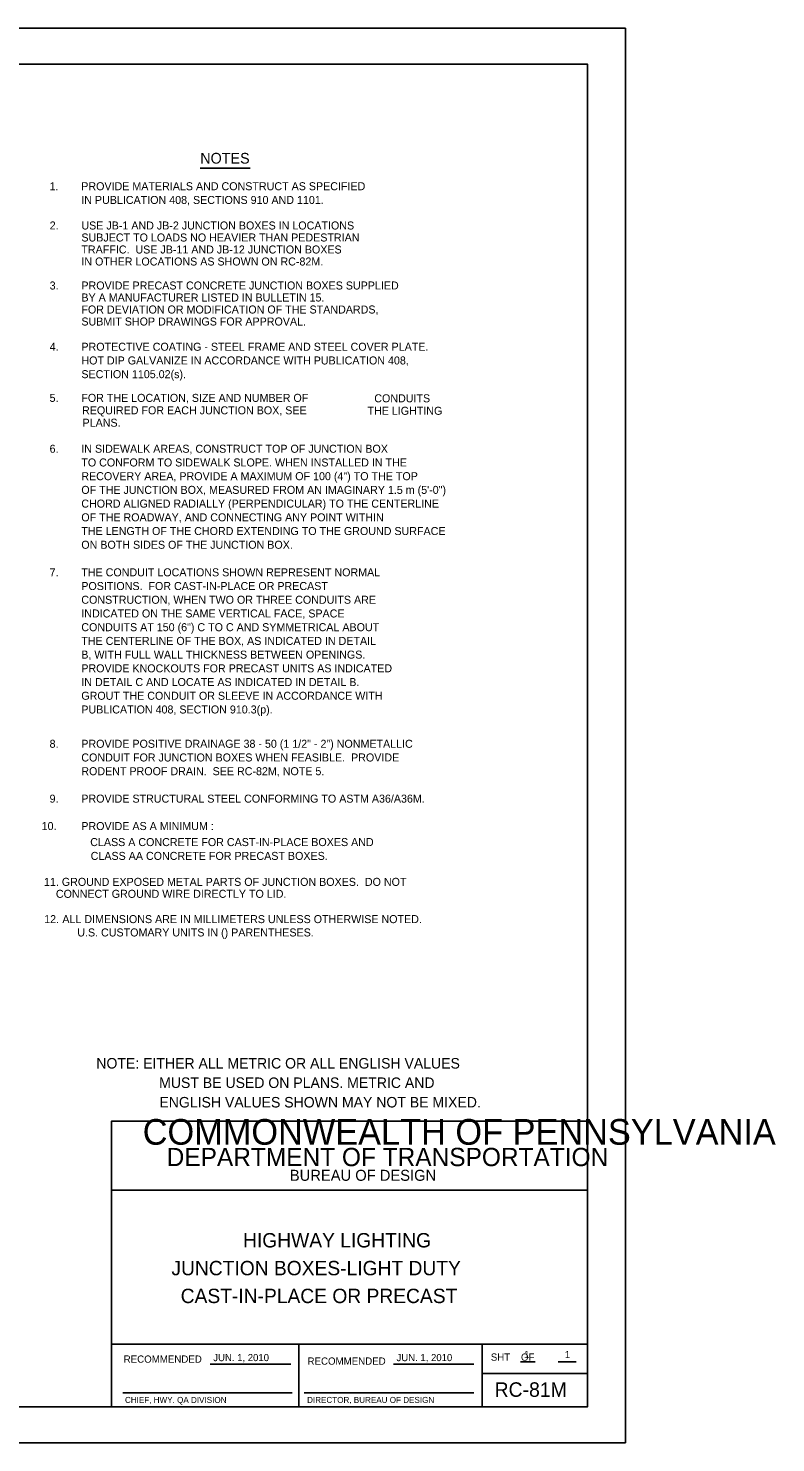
# Model space of a CAD drawing. Extents: x 638447 to 639352, y 298406 to 299000.
# Drawn here: x 639037 to 639352, y 298406 to 299000 of the extents above; entities that cross this region are included whole.
import ezdxf

# ---------------------------------------------------------------- set-up
doc = ezdxf.new("R2010")
doc.units = 0
for name, color, linetype in [('1', 7, 'Continuous'), ('2', 7, 'Continuous'), ('3', 7, 'Continuous'), ('40', 7, 'Continuous'), ('PLT-BNDY', 7, 'Continuous')]:
    doc.layers.add(name, color=color, linetype=linetype)

msp = doc.modelspace()

# ---------------------------------------------------------------- linework, layer by layer
at = {"layer": '1'}
for p, q in [((639113.859625, 298439.4615), (639147.746125, 298439.4615)), ((639190.857625, 298439.4615), (639224.727625, 298439.4615)), ((639244.260125, 298440.4455), (639250.402125, 298440.4455)), ((639260.069625, 298440.4455), (639267.716125, 298440.4455)), ((639077.156625, 298427.428146), (639148.406125, 298427.428146)), ((639153.326125, 298427.428146), (639224.666125, 298427.428146))]:
    msp.add_line(p, q, dxfattribs=at)
msp.add_lwpolyline([(639272.394625, 298421.4725), (639272.394625, 298985.4725), (638486.394625, 298985.4725), (638486.394625, 298421.4725), (639272.394625, 298421.4725), (639272.394625, 298447.8315), (639072.394625, 298447.8315), (639072.394625, 298512.509), (639272.394625, 298512.509), (639272.394625, 298541.4725), (639072.394625, 298541.4725), (639072.394625, 298421.4725), (639151.196125, 298421.4725), (639151.196125, 298447.8315), (639151.196125, 298421.4725), (639228.196125, 298421.4725), (639228.196125, 298447.8315), (639228.196125, 298435.515), (639272.394625, 298435.515)], dxfattribs=at)
at = {"layer": '3'}
msp.add_line((639109.689875, 298941.762), (639130.687875, 298941.762), dxfattribs=at)
at = {"layer": 'PLT-BNDY'}
msp.add_lwpolyline([(638447.394625, 299000.4725), (639288.394625, 299000.4725), (639288.394625, 298406.4725), (638447.394625, 298406.4725)], close=True, dxfattribs=at)

# ---------------------------------------------------------------- texts
at = {"layer": '1'}
for s, height, p in [('12.', 3.36, (639044.140875, 298624.67125)), ('COMMONWEALTH OF PENNSYLVANIA', 10.7833725, (639085.545625, 298531.616)), ('DEPARTMENT OF TRANSPORTATION', 7.6842885, (639095.606625, 298522.62175)), ('BUREAU OF DESIGN', 4.6220925, (639147.381125, 298516.4595)), ('HIGHWAY LIGHTING', 6.0400005, (639127.717125, 298488.4795)), ('JUNCTION BOXES-LIGHT DUTY', 6.0400005, (639097.614375, 298476.7915)), ('CAST-IN-PLACE OR PRECAST', 6.0400005, (639101.507125, 298465.10325)), ('JUN. 1, 2010', 3, (639115.198151, 298440.719402)), ('JUN. 1, 2010', 3, (639192.196151, 298440.719402)), ('SHT    OF', 3.048, (639231.800125, 298440.9025)), ('1', 3.048, (639245.792125, 298441.98675)), ('1', 3.048, (639262.919625, 298441.98675)), ('RECOMMENDED', 3.048, (639077.558125, 298440.066)), ('RECOMMENDED', 3.048, (639154.802125, 298439.22975)), ('RC-81M', 6.096, (639233.392125, 298425.7375)), ('CHIEF, HWY. QA DIVISION', 2.5399995, (639078.107946, 298423.170146)), ('DIRECTOR, BUREAU OF DESIGN', 2.5399995, (639154.625399, 298423.170146))]:
    msp.add_text(s, height=height, dxfattribs=at).set_placement(p)
at = {"layer": '2'}
for s, height, p in [('1.  ', 3.359988, (639046.406625, 298932.4595)), ('PROVIDE MATERIALS AND CONSTRUCT AS SPECIFIED', 3.359988, (639059.740625, 298932.459512)), ('IN PUBLICATION 408, SECTIONS 910 AND 1101.', 3.359988, (639059.740625, 298926.699524)), ('PROTECTIVE COATING - STEEL FRAME AND STEEL COVER PLATE.', 3.359988, (639059.794625, 298865.055)), ('HOT DIP GALVANIZE IN ACCORDANCE WITH PUBLICATION 408,', 3.359988, (639059.794625, 298859.295)), ('SECTION 1105.02(s).', 3.359988, (639059.794625, 298853.535)), ('IN SIDEWALK AREAS, CONSTRUCT TOP OF JUNCTION BOX', 3.359988, (639059.758625, 298822.217)), ('TO CONFORM TO SIDEWALK SLOPE. WHEN INSTALLED IN THE', 3.359988, (639059.758625, 298816.457)), ('RECOVERY AREA, PROVIDE A MAXIMUM OF 100 (4") TO THE TOP', 3.359988, (639059.758625, 298810.697)), ('OF THE JUNCTION BOX, MEASURED FROM AN IMAGINARY 1.5 m (5\'-0")', 3.359988, (639059.758625, 298804.937)), ('CHORD ALIGNED RADIALLY (PERPENDICULAR) TO THE CENTERLINE', 3.359988, (639059.758625, 298799.177)), ('OF THE ROADWAY, AND CONNECTING ANY POINT WITHIN', 3.359988, (639059.758625, 298793.417)), ('THE LENGTH OF THE CHORD EXTENDING TO THE GROUND SURFACE', 3.359988, (639059.758625, 298787.657)), ('ON BOTH SIDES OF THE JUNCTION BOX.', 3.359988, (639059.758625, 298781.897)), ('THE CONDUIT LOCATIONS SHOWN REPRESENT NORMAL', 3.359988, (639059.758625, 298770.321)), ('POSITIONS.  FOR CAST-IN-PLACE OR PRECAST', 3.359988, (639059.758625, 298764.561)), ('CONSTRUCTION, WHEN TWO OR THREE CONDUITS ARE', 3.359988, (639059.758625, 298758.801)), ('INDICATED ON THE SAME VERTICAL FACE, SPACE', 3.359988, (639059.758625, 298753.041)), ('CONDUITS AT 150 (6") C TO C AND SYMMETRICAL ABOUT', 3.359988, (639059.758625, 298747.281)), ('THE CENTERLINE OF THE BOX, AS INDICATED IN DETAIL', 3.359988, (639059.758625, 298741.521)), ('B, WITH FULL WALL THICKNESS BETWEEN OPENINGS.', 3.359988, (639059.758625, 298735.761)), ('PROVIDE KNOCKOUTS FOR PRECAST UNITS AS INDICATED', 3.359988, (639059.758625, 298730.001)), ('IN DETAIL C AND LOCATE AS INDICATED IN DETAIL B.', 3.359988, (639059.758625, 298724.241)), ('GROUT THE CONDUIT OR SLEEVE IN ACCORDANCE WITH', 3.359988, (639059.758625, 298718.481)), ('PUBLICATION 408, SECTION 910.3(p).', 3.359988, (639059.758625, 298712.721)), ('8.  ', 3.359988, (639046.424625, 298698.321)), ('PROVIDE POSITIVE DRAINAGE 38 - 50 (1 1/2" - 2") NONMETALLIC', 3.359988, (639059.758625, 298698.321012)), ('CONDUIT FOR JUNCTION BOXES WHEN FEASIBLE.  PROVIDE', 3.359988, (639059.758625, 298692.561024)), ('RODENT PROOF DRAIN.  SEE RC-82M, NOTE 5.', 3.359988, (639059.758625, 298686.801036)), ('9.  ', 3.359988, (639046.424625, 298675.281)), ('PROVIDE STRUCTURAL STEEL CONFORMING TO ASTM A36/A36M.', 3.36, (639059.758625, 298675.281)), ('10.  ', 3.359988, (639043.090625, 298663.761)), ('PROVIDE AS A MINIMUM :', 3.359988, (639059.758625, 298663.761)), ('   CLASS A CONCRETE FOR CAST-IN-PLACE BOXES AND', 3.36, (639059.758625, 298657.029)), ('   CLASS AA CONCRETE FOR PRECAST BOXES.', 3.36, (639059.944625, 298651.229)), ('11. GROUND EXPOSED METAL PARTS OF JUNCTION BOXES.  DO NOT', 3.36, (639044.082625, 298640.325)), ('    CONNECT GROUND WIRE DIRECTLY TO LID.', 3.36, (639044.082625, 298635.305)), ('   ALL DIMENSIONS ARE IN MILLIMETERS UNLESS OTHERWISE NOTED.', 3.36, (639048.050875, 298624.68275))]:
    msp.add_text(s, height=height, dxfattribs=at).set_placement(p)
at = {"layer": '3'}
for s, height, p in [('NOTES', 4.5, (639109.740125, 298943.65075)), ('2.  ', 3.359988, (639046.460625, 298915.9745)), ('USE JB-1 AND JB-2 JUNCTION BOXES IN LOCATIONS', 3.359988, (639059.794625, 298915.9745)), ('SUBJECT TO LOADS NO HEAVIER THAN PEDESTRIAN', 3.359988, (639059.794625, 298910.9345)), ('TRAFFIC.  USE JB-11 AND JB-12 JUNCTION BOXES', 3.359988, (639059.794625, 298905.8945)), ('IN OTHER LOCATIONS AS SHOWN ON RC-82M.', 3.359988, (639059.794625, 298900.8545)), ('3.  ', 3.359988, (639046.460625, 298890.7745)), ('PROVIDE PRECAST CONCRETE JUNCTION BOXES SUPPLIED', 3.359988, (639059.794625, 298890.7745)), ('BY A MANUFACTURER LISTED IN BULLETIN 15.', 3.359988, (639059.794625, 298885.7345)), ('FOR DEVIATION OR MODIFICATION OF THE STANDARDS,', 3.359988, (639059.794625, 298880.6945)), ('SUBMIT SHOP DRAWINGS FOR APPROVAL.', 3.359988, (639059.794625, 298875.6545)), ('4.  ', 3.359988, (639046.460625, 298865.055)), ('5.  ', 3.359988, (639046.424625, 298843.577)), ('FOR THE LOCATION, SIZE AND NUMBER OF', 3.359988, (639059.758625, 298843.577)), ('REQUIRED FOR EACH JUNCTION BOX, SEE', 3.359988, (639060.062625, 298838.353)), ('THE LIGHTING ', 3.359988, (639179.984625, 298838.161)), ('CONDUITS ', 3.359988, (639182.850625, 298843.403)), ('PLANS.', 3.359988, (639060.266625, 298833.147)), ('6.  ', 3.359988, (639046.424625, 298822.217)), ('IN', 3.359988, (639059.758625, 298822.217)), ('7.  ', 3.359988, (639046.424625, 298770.321))]:
    msp.add_text(s, height=height, dxfattribs=at).set_placement(p)
at = {"layer": '40'}
for s, height, p in [('U.S. CUSTOMARY UNITS IN () PARENTHESES.', 3.36, (639058.061125, 298619.0815)), ('NOTE: EITHER ALL METRIC OR ALL ENGLISH VALUES', 4.4114085, (639066.060875, 298563.609)), ('MUST BE USED ON PLANS. METRIC AND', 4.4114085, (639092.457125, 298555.44675)), ('ENGLISH VALUES SHOWN MAY NOT BE MIXED.', 4.4114085, (639092.567125, 298547.25875))]:
    msp.add_text(s, height=height, dxfattribs=at).set_placement(p)

doc.saveas('drawing.dxf')
